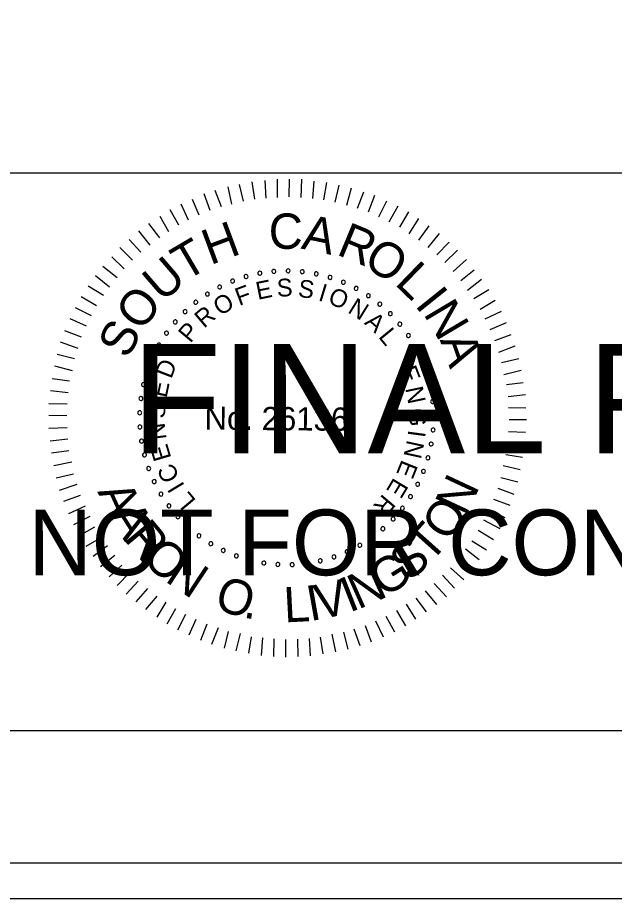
# Model space of a CAD drawing. Extents: x 967 to 1326, y 964 to 2024.
# Drawn here: x 1170.56 to 1189.3, y 1523.72 to 1551.36 of the extents above; entities that cross this region are included whole.
import ezdxf

# ---------------------------------------------------------------- set-up
doc = ezdxf.new("R2010")
doc.units = 0
for name, color, linetype in [('RD_SHT_Bndy', 7, 'Continuous'), ('RD_SHT_IplotShp', 7, 'Continuous'), ('RD_SHT_Misc1', 7, 'Continuous'), ('RD_SHT_Misc2', 7, 'Continuous'), ('RD_Sketch1', 7, 'Continuous')]:
    doc.layers.add(name, color=color, linetype=linetype)

msp = doc.modelspace()

# ---------------------------------------------------------------- linework, layer by layer
at = {"layer": 'RD_SHT_Bndy'}
for p, q in [((996.114, 1546.486), (1323.886, 1546.486)), ((1323.886, 1528.983), (996.114, 1528.983))]:
    msp.add_line(p, q, dxfattribs=at)
at = {"layer": 'RD_SHT_IplotShp'}
for points in [[(967.409, 1523.72), (1326.285, 1523.72), (1326.285, 1743.72), (967.409, 1743.72)], [(988.525, 1524.84), (1326.285, 1524.84), (1326.285, 1742.6), (988.525, 1742.6)]]:
    msp.add_lwpolyline(points, close=True, dxfattribs=at)
at = {"layer": 'RD_SHT_Misc1'}
for p, q in [((1178.01, 1545.663), (1177.93, 1546.209)), ((1178.364, 1545.699), (1178.33, 1546.244)), ((1178.717, 1545.719), (1178.722, 1546.295)), ((1179.093, 1545.739), (1179.098, 1546.292)), ((1179.469, 1545.713), (1179.489, 1546.288)), ((1179.829, 1545.687), (1179.872, 1546.231)), ((1180.174, 1545.646), (1180.271, 1546.19)), ((1176.964, 1545.419), (1176.769, 1545.935)), ((1177.287, 1545.508), (1177.169, 1546.054)), ((1177.657, 1545.597), (1177.53, 1546.128)), ((1180.535, 1545.573), (1180.662, 1546.102)), ((1180.902, 1545.478), (1181.045, 1546.022)), ((1181.231, 1545.384), (1181.428, 1545.896)), ((1176.264, 1545.156), (1176.053, 1545.657)), ((1176.61, 1545.306), (1176.423, 1545.83)), ((1181.584, 1545.265), (1181.78, 1545.786)), ((1175.933, 1545.005), (1175.699, 1545.506)), ((1181.905, 1545.109), (1182.154, 1545.606)), ((1182.226, 1544.953), (1182.506, 1545.45)), ((1175.308, 1544.634), (1175.036, 1545.12)), ((1175.624, 1544.846), (1175.352, 1545.332)), ((1182.562, 1544.789), (1182.85, 1545.27)), ((1175.03, 1544.445), (1174.681, 1544.9)), ((1182.86, 1544.572), (1183.163, 1545.053)), ((1183.158, 1544.378), (1183.484, 1544.828)), ((1174.729, 1544.217), (1174.372, 1544.665)), ((1183.447, 1544.145), (1183.811, 1544.587)), ((1174.435, 1543.997), (1174.062, 1544.399)), ((1183.729, 1543.92), (1184.116, 1544.316)), ((1174.172, 1543.753), (1173.776, 1544.148)), ((1183.98, 1543.672), (1184.368, 1544.061)), ((1173.909, 1543.479), (1173.52, 1543.858)), ((1184.232, 1543.394), (1184.657, 1543.767)), ((1173.684, 1543.197), (1173.242, 1543.546)), ((1184.475, 1543.108), (1184.892, 1543.45)), ((1173.451, 1542.9), (1173.009, 1543.256)), ((1184.687, 1542.807), (1185.128, 1543.156)), ((1173.257, 1542.64), (1172.776, 1542.936)), ((1173.039, 1542.312), (1172.559, 1542.6)), ((1184.885, 1542.544), (1185.355, 1542.832)), ((1185.081, 1542.213), (1185.56, 1542.493)), ((1172.883, 1542.006), (1172.379, 1542.256)), ((1185.24, 1541.904), (1185.756, 1542.145)), ((1172.727, 1541.677), (1172.215, 1541.904)), ((1185.399, 1541.573), (1185.907, 1541.791)), ((1172.571, 1541.333), (1172.051, 1541.53)), ((1185.549, 1541.226), (1186.057, 1541.414)), ((1172.461, 1540.974), (1171.91, 1541.178)), ((1185.669, 1540.865), (1186.185, 1541.06)), ((1172.351, 1540.652), (1171.807, 1540.787)), ((1185.759, 1540.541), (1186.297, 1540.667)), ((1172.286, 1540.276), (1171.727, 1540.419)), ((1185.832, 1540.165), (1186.371, 1540.298)), ((1172.191, 1539.955), (1171.647, 1540.029)), ((1185.906, 1539.842), (1186.436, 1539.906)), ((1172.15, 1539.587), (1171.598, 1539.653)), ((1185.964, 1539.473), (1186.51, 1539.53)), ((1172.124, 1539.234), (1171.548, 1539.239)), ((1185.977, 1539.12), (1186.514, 1539.115)), ((1172.105, 1538.866), (1171.545, 1538.871)), ((1185.997, 1538.751), (1186.542, 1538.747)), ((1172.118, 1538.482), (1171.542, 1538.471)), ((1185.971, 1538.368), (1186.508, 1538.348)), ((1172.138, 1538.136), (1171.585, 1538.072)), ((1185.952, 1538.022), (1186.497, 1537.949)), ((1172.173, 1537.768), (1171.627, 1537.688)), ((1185.888, 1537.655), (1186.417, 1537.566)), ((1172.262, 1537.414), (1171.701, 1537.296)), ((1185.808, 1537.302), (1186.345, 1537.175)), ((1172.321, 1537.037), (1171.774, 1536.911)), ((1185.729, 1536.926), (1186.265, 1536.792)), ((1172.425, 1536.707), (1171.871, 1536.519)), ((1185.634, 1536.597), (1186.146, 1536.401)), ((1172.53, 1536.36), (1172.007, 1536.173)), ((1185.508, 1536.253), (1186.013, 1536.057)), ((1172.681, 1536.029), (1172.165, 1535.788)), ((1172.831, 1535.705), (1172.323, 1535.441)), ((1185.352, 1535.924), (1185.857, 1535.675)), ((1185.188, 1535.603), (1185.7, 1535.33)), ((1172.982, 1535.374), (1172.497, 1535.094)), ((1185.024, 1535.274), (1185.498, 1534.987)), ((1173.194, 1535.042), (1172.709, 1534.762)), ((1184.822, 1534.946), (1185.288, 1534.658)), ((1173.384, 1534.78), (1172.936, 1534.453)), ((1184.62, 1534.687), (1185.055, 1534.353)), ((1173.612, 1534.478), (1173.164, 1534.129)), ((1184.403, 1534.389), (1184.814, 1534.033)), ((1173.832, 1534.177), (1173.437, 1533.812)), ((1184.155, 1534.092), (1184.574, 1533.72)), ((1174.091, 1533.945), (1173.689, 1533.541)), ((1183.899, 1533.864), (1184.28, 1533.454)), ((1174.35, 1533.674), (1173.97, 1533.263)), ((1183.644, 1533.597), (1184.024, 1533.18)), ((1174.64, 1533.442), (1174.275, 1533.022)), ((1174.937, 1533.209), (1174.58, 1532.782)), ((1183.358, 1533.37), (1183.715, 1532.944)), ((1175.212, 1533.014), (1174.932, 1532.549)), ((1182.764, 1532.952), (1183.059, 1532.482)), ((1183.065, 1533.141), (1183.384, 1532.709)), ((1175.525, 1532.812), (1175.245, 1532.331)), ((1175.83, 1532.633), (1175.588, 1532.136)), ((1182.463, 1532.755), (1182.743, 1532.269)), ((1176.159, 1532.477), (1175.94, 1531.98)), ((1181.8, 1532.431), (1182.041, 1531.93)), ((1182.124, 1532.581), (1182.396, 1532.08)), ((1176.503, 1532.321), (1176.307, 1531.816)), ((1176.855, 1532.211), (1176.651, 1531.69)), ((1177.177, 1532.1), (1177.05, 1531.572)), ((1181.122, 1532.175), (1181.31, 1531.652)), ((1181.476, 1532.28), (1181.664, 1531.771)), ((1177.545, 1532.036), (1177.409, 1531.484)), ((1177.897, 1531.933), (1177.808, 1531.412)), ((1178.25, 1531.892), (1178.207, 1531.34)), ((1178.603, 1531.866), (1178.598, 1531.313)), ((1178.978, 1531.84), (1178.974, 1531.295)), ((1179.355, 1531.86), (1179.365, 1531.307)), ((1179.715, 1531.88), (1179.749, 1531.327)), ((1180.061, 1531.915), (1180.149, 1531.393)), ((1180.423, 1532.012), (1180.541, 1531.458)), ((1180.791, 1532.07), (1180.926, 1531.54))]:
    msp.add_line(p, q, dxfattribs=at)
for centre, start, end in [((1178.609, 1543.397), 5.0653, 185.0653), ((1179.055, 1543.414), 359.5268, 179.5268), ((1179.055, 1543.414), 179.5268, 359.5268), ((1179.5, 1543.388), 353.9884, 173.9884), ((1177.312, 1543.091), 21.6807, 201.6807), ((1177.734, 1543.235), 16.1422, 196.1422), ((1177.734, 1543.235), 196.1422, 16.1422), ((1178.168, 1543.337), 10.6038, 190.6038), ((1178.168, 1543.337), 190.6038, 10.6038), ((1178.609, 1543.397), 185.0653, 5.0653), ((1179.5, 1543.388), 173.9884, 353.9884), ((1179.94, 1543.319), 168.4499, 348.4499), ((1179.94, 1543.319), 348.4499, 168.4499), ((1180.372, 1543.208), 162.9114, 342.9114), ((1180.372, 1543.208), 342.9114, 162.9114), ((1176.906, 1542.908), 27.2191, 207.2191), ((1176.906, 1542.908), 207.2191, 27.2191), ((1177.312, 1543.091), 201.6807, 21.6807), ((1180.79, 1543.056), 157.373, 337.373), ((1180.79, 1543.056), 337.373, 157.373), ((1181.193, 1542.864), 151.8345, 331.8345), ((1181.193, 1542.864), 331.8345, 151.8345), ((1176.52, 1542.686), 32.7576, 212.7576), ((1176.52, 1542.686), 212.7576, 32.7576), ((1181.574, 1542.634), 146.2961, 326.2961), ((1181.574, 1542.634), 326.2961, 146.2961), ((1176.156, 1542.428), 38.2961, 218.2961), ((1176.156, 1542.428), 218.2961, 38.2961), ((1181.932, 1542.368), 140.7576, 320.7576), ((1181.932, 1542.368), 320.7576, 140.7576), ((1175.82, 1542.135), 43.8345, 223.8345), ((1175.82, 1542.135), 223.8345, 43.8345), ((1182.263, 1542.069), 135.2191, 315.2191), ((1182.263, 1542.069), 315.2191, 135.2191), ((1175.513, 1541.812), 49.373, 229.373), ((1175.513, 1541.812), 229.373, 49.373), ((1182.563, 1541.74), 129.6807, 309.6807), ((1182.563, 1541.74), 309.6807, 129.6807), ((1175.239, 1541.461), 54.9114, 234.9114), ((1175.239, 1541.461), 234.9114, 54.9114), ((1182.83, 1541.383), 124.1422, 304.1422), ((1182.83, 1541.383), 304.1422, 124.1422), ((1175, 1541.085), 60.4499, 240.4499), ((1175, 1541.085), 240.4499, 60.4499), ((1183.061, 1541.002), 118.6038, 298.6038), ((1183.061, 1541.002), 298.6038, 118.6038), ((1174.798, 1540.687), 65.9884, 245.9884), ((1174.798, 1540.687), 245.9884, 65.9884), ((1183.255, 1540.601), 113.0653, 293.0653), ((1183.255, 1540.601), 293.0653, 113.0653), ((1174.636, 1540.272), 71.5268, 251.5268), ((1174.636, 1540.272), 251.5268, 71.5268), ((1183.408, 1540.182), 107.5268, 287.5268), ((1183.408, 1540.182), 287.5268, 107.5268), ((1174.514, 1539.843), 77.0653, 257.0653), ((1174.514, 1539.843), 257.0653, 77.0653), ((1183.521, 1539.751), 101.9884, 281.9884), ((1183.521, 1539.751), 281.9884, 101.9884), ((1174.435, 1539.405), 82.6038, 262.6038), ((1174.435, 1539.405), 262.6038, 82.6038), ((1183.592, 1539.311), 96.4499, 276.4499), ((1183.592, 1539.311), 276.4499, 96.4499), ((1174.398, 1538.961), 88.1422, 268.1422), ((1174.398, 1538.961), 268.1422, 88.1422), ((1183.619, 1538.866), 90.9114, 270.9114), ((1183.619, 1538.866), 270.9114, 90.9114), ((1174.404, 1538.515), 93.6807, 273.6807), ((1174.404, 1538.515), 273.6807, 93.6807), ((1183.604, 1538.421), 85.373, 265.373), ((1183.604, 1538.421), 265.373, 85.373), ((1174.453, 1538.072), 99.2191, 279.2191), ((1174.453, 1538.072), 279.2191, 99.2191), ((1183.546, 1537.979), 79.8345, 259.8345), ((1183.546, 1537.979), 259.8345, 79.8345), ((1174.545, 1537.636), 104.7576, 284.7576), ((1174.545, 1537.636), 284.7576, 104.7576), ((1183.445, 1537.545), 74.2961, 254.2961), ((1183.445, 1537.545), 254.2961, 74.2961), ((1174.678, 1537.211), 110.2961, 290.2961), ((1174.678, 1537.211), 290.2961, 110.2961), ((1183.303, 1537.122), 68.7576, 248.7576), ((1183.303, 1537.122), 248.7576, 68.7576), ((1174.852, 1536.8), 115.8345, 295.8345), ((1174.852, 1536.8), 295.8345, 115.8345), ((1183.121, 1536.716), 63.2191, 243.2191), ((1183.121, 1536.716), 243.2191, 63.2191), ((1175.065, 1536.409), 121.373, 301.373), ((1175.065, 1536.409), 301.373, 121.373), ((1182.9, 1536.328), 57.6807, 237.6807), ((1182.9, 1536.328), 237.6807, 57.6807), ((1175.314, 1536.039), 126.9114, 306.9114), ((1175.314, 1536.039), 306.9114, 126.9114), ((1182.643, 1535.964), 52.1422, 232.1422), ((1182.643, 1535.964), 232.1422, 52.1422), ((1175.598, 1535.696), 132.4499, 312.4499), ((1175.598, 1535.696), 312.4499, 132.4499), ((1182.353, 1535.627), 46.6038, 226.6038), ((1182.353, 1535.627), 226.6038, 46.6038), ((1175.914, 1535.381), 137.9884, 317.9884), ((1175.914, 1535.381), 317.9884, 137.9884), ((1176.258, 1535.099), 143.5268, 323.5268), ((1176.258, 1535.099), 323.5268, 143.5268), ((1182.03, 1535.319), 41.0653, 221.0653), ((1182.03, 1535.319), 221.0653, 41.0653), ((1176.629, 1534.851), 149.0653, 329.0653), ((1176.629, 1534.851), 329.0653, 149.0653), ((1181.305, 1534.803), 29.9884, 209.9884), ((1181.68, 1535.043), 35.5268, 215.5268), ((1181.68, 1535.043), 215.5268, 35.5268), ((1177.021, 1534.639), 154.6038, 334.6038), ((1177.021, 1534.639), 334.6038, 154.6038), ((1180.908, 1534.6), 24.4499, 204.4499), ((1180.908, 1534.6), 204.4499, 24.4499), ((1181.305, 1534.803), 209.9884, 29.9884), ((1177.432, 1534.467), 160.1422, 340.1422), ((1177.432, 1534.467), 340.1422, 160.1422), ((1177.858, 1534.335), 165.6807, 345.6807), ((1177.858, 1534.335), 345.6807, 165.6807), ((1178.294, 1534.245), 351.2191, 171.2191), ((1179.627, 1534.232), 7.8345, 187.8345), ((1180.065, 1534.313), 13.373, 193.373), ((1180.065, 1534.313), 193.373, 13.373), ((1180.494, 1534.436), 18.9114, 198.9114), ((1180.494, 1534.436), 198.9114, 18.9114), ((1178.294, 1534.245), 171.2191, 351.2191), ((1178.737, 1534.198), 356.7576, 176.7576), ((1178.737, 1534.198), 176.7576, 356.7576), ((1179.183, 1534.193), 2.2961, 182.2961), ((1179.183, 1534.193), 182.2961, 2.2961), ((1179.627, 1534.232), 187.8345, 7.8345)]:
    msp.add_arc(centre, 0.0627, start, end, dxfattribs=at)
at = {"layer": 'RD_Sketch1'}
msp.add_lwpolyline([(967.409, 1523.72), (1326.285, 1523.72), (1326.285, 1743.72), (967.409, 1743.72)], close=True, dxfattribs=at)

# ---------------------------------------------------------------- texts
at = {"layer": 'RD_SHT_Misc1'}
for s, height, rotation, p in [('C', 1.11, 359.5482, (1178.442, 1544.108)), ('A', 1.11, 348.1981, (1179.439, 1544.115)), ('H', 1.11, 20.3637, (1176.614, 1543.587)), ('R', 1.11, 337.4344, (1180.541, 1543.937)), ('T', 1.11, 30.4992, (1175.828, 1543.072)), ('O', 1.108, 326.5869, (1181.366, 1543.609)), ('U', 1.11, 40.8022, (1175.102, 1542.403)), ('L', 1.11, 315.9488, (1182.373, 1543.003)), ('E', 0.557, 11.4103, (1178.103, 1542.503)), ('S', 0.557, 2.208, (1178.709, 1542.601)), ('S', 0.557, 352.6608, (1179.346, 1542.599)), ('F', 0.557, 20.6127, (1177.52, 1542.309)), ('I', 0.557, 343.1136, (1179.975, 1542.491)), ('O', 0.557, 338.4392, (1180.274, 1542.401)), ('I', 1.11, 308.6613, (1183.011, 1542.338)), ('O', 1.11, 52.0267, (1174.435, 1541.474)), ('O', 0.557, 30.8477, (1176.917, 1541.987)), ('N', 0.557, 328.2042, (1180.896, 1542.12)), ('N', 1.11, 300.7037, (1183.285, 1542.075)), ('R', 0.557, 40.3949, (1176.415, 1541.594)), ('A', 0.557, 318.657, (1181.424, 1541.762)), ('S', 1.108, 63.2511, (1174.029, 1540.619)), ('P', 0.557, 49.9421, (1175.985, 1541.124)), ('L', 0.557, 309.4546, (1181.869, 1541.339)), ('A', 1.11, 289.4792, (1183.814, 1541.243)), ('D', 0.557, 69.0364, (1175.386, 1540.003)), ('E', 0.557, 291.049, (1182.53, 1540.307)), ('E', 0.557, 78.2388, (1175.238, 1539.407)), ('N', 0.557, 281.8466, (1182.728, 1539.726)), ('S', 0.557, 87.786, (1175.187, 1538.772)), ('No. 26136', 0.7311, 359.5268, (1176.429, 1538.43)), ('G', 0.557, 272.2995, (1182.833, 1539.097)), ('N', 0.557, 97.3332, (1175.242, 1538.137)), ('I', 0.557, 262.4084, (1182.83, 1538.437)), ('E', 0.557, 106.5355, (1175.394, 1537.541)), ('N', 0.557, 257.7339, (1182.789, 1538.127)), ('C', 0.557, 116.4266, (1175.661, 1536.938)), ('E', 0.557, 248.1867, (1182.628, 1537.511)), ('I', 0.557, 121.1011, (1175.823, 1536.67)), ('E', 0.557, 238.9844, (1182.378, 1536.949)), ('N', 1.105, 64.8922, (1184.632, 1535.684)), ('A', 1.105, 294.7297, (1173.062, 1536.486)), ('L', 0.557, 129.9595, (1176.187, 1536.204)), ('R', 0.557, 229.782, (1182.041, 1536.435)), ('O', 1.105, 56.2059, (1184.102, 1534.874)), ('A', 1.105, 302.2892, (1173.414, 1535.72)), ('R', 1.105, 309.8487, (1173.865, 1535.007)), ('T', 1.105, 48.2685, (1183.515, 1534.211)), ('O', 1.105, 317.7861, (1174.434, 1534.33)), ('S', 1.105, 40.3311, (1182.842, 1533.636)), ('N', 1.105, 326.4725, (1175.158, 1533.686)), ('G', 1.105, 32.0198, (1182.059, 1533.14)), ('N', 1.105, 24.0824, (1181.252, 1532.776)), ('O', 1.105, 342.3472, (1176.697, 1532.82)), ('V', 1.105, 12.7741, (1180.033, 1532.457)), ('I', 1.105, 21.4605, (1180.976, 1532.681)), ('L', 1.105, 2.9677, (1178.943, 1532.379)), ('I', 1.105, 10.1523, (1179.743, 1532.418)), ('.', 1.105, 351.0336, (1177.623, 1532.536))]:
    msp.add_text(s, height=height, rotation=rotation, dxfattribs=at).set_placement(p)
at = {"layer": 'RD_SHT_Misc2'}
for s, height, p in [('FINAL PLANS', 3.4375, (1174.145, 1537.685)), ('NOT FOR CONSTRUCTION', 2.0625, (1170.901, 1533.86))]:
    msp.add_text(s, height=height, dxfattribs=at).set_placement(p)

doc.saveas('drawing.dxf')
